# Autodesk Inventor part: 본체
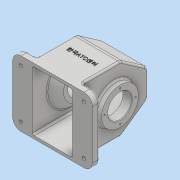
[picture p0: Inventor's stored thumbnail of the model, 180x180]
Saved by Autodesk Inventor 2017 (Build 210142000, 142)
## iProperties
Part Number: 본체
Material: 일반
Document SubType Name: Modeling
Designer: MRC
Density: 1 g/cm^3
Appearance: 기본값
Author: MRC
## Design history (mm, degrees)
sketch "스케치4"
  geometry: L1 (38.5, -55)-(-38.5, -55); L2 (-38.5, -55)-(-38.5, 55); L3 (-38.5, 55)-(38.5, 55); L4 (38.5, 55)-(38.5, -55); L5 (38.5, -55)-(-38.5, 55); L6 (-38.5, -55)-(38.5, 55); 1 further point
  constraints: 12 end point, 2 midpoint, 2 parallel, 1 horizontal, 1 perpendicular
  dimensions: "d12" = 110 distance of L3.end L1.start; "d13" = 77 distance of L1.start L1.end
extrude "돌출4" new body sketch "스케치4" distance "d14" = 122; taper "d15" = 0 deg
sketch "스케치5"
  geometry: L1 (0, 77)-(31.509, 122); L2 (0, 0)-(0, 122) reference; L3 (110, 0)-(0, 0) reference; L4 (0, 122)-(110, 122) reference; 1 further point
  constraints: 2 end point, 2 point on line
  dimensions: "d16" = 35 deg angle of L1 L2; "d17" = 77 distance from line of L3 L1.start
extrude "돌출5" cut sketch "스케치5" distance "d18" = 122; taper "d19" = 0 deg
feature "쉘1" dims "d20" = 5
sketch "스케치7"
  geometry: L1 (-38.5, 55)-(-38.5, -55) reference; L2 (38.5, 55)-(-38.5, 55) reference; L3 (-38.5, 55)-(-67, 55); L4 (-67, 55)-(-67, -55); L5 (-38.5, -55)-(38.5, -55) reference; L6 (-67, -55)-(-38.5, -55); 1 further point
  constraints: 6 end point, 2 perpendicular, 1 horizontal
  dimensions: "d25" = 67 distance from line of L4 point (0, 0)
extrude "돌출7" join sketch "스케치7" distance "d26" = 12; taper "d27" = 0 deg
node "작업 평면1"
sketch "스케치8"
  geometry: L1 (-26.509, -122)-(73.491, -122) reference; C1 r 37.5 at (23.491, -57); 1 further point
  constraints: 1 centre point, 1 vertical alignment
  dimensions: "d29" = 75 diameter of C1; "d30" = 65 distance from line of L1 C1.centre
extrude "돌출8" join sketch "스케치8" stored distance "d31" = 12; taper "d32" = 0 deg
sketch "스케치9"
  geometry: L1 (-55, -65)-(55, -65) reference; C1 r 37.5 at (0, 0) reference; 3 further points
  constraints: 1 midpoint, 1 vertical alignment
  dimensions: "d33" = 29 distance of C1.centre point (0, 29)
hole "구멍1" sketch "스케치9" at (0, 29) diameter "d34" = 2.459; stored, may be unused: countersink angle "d38" = 90 deg, drill point angle "d40" = 118 deg; dims "d35" = 6, "d36" = 4, "d37" = 2, "d39" = 8
node "작업 평면2"
sketch "스케치10"
  geometry: L1 (78.491, -122)-(-31.509, -122) reference; C1 r 31 at (23.491, -57); 2 further points
  constraints: 1 centre point, 1 midpoint, 1 vertical alignment
  dimensions: "d45" = 62 diameter of C1; "d46" = 65 distance from line of C1.centre L1
extrude "돌출9" join sketch "스케치10" distance "d47" = 10; taper "d48" = 0 deg
sketch "스케치11"
  geometry: C1 r 31 at (0, 0) reference; 2 further points
  constraints: 1 vertical alignment
  dimensions: "d49" = 26 distance of C1.centre point (0, 26)
hole "구멍2" sketch "스케치11" at (0, 26) diameter "d50" = 2.459; stored, may be unused: countersink angle "d54" = 90 deg, drill point angle "d56" = 118 deg; dims "d51" = 6, "d52" = 4, "d53" = 2, "d55" = 8
node "작업 평면3"
sketch "스케치13"
  geometry: C1 r 31 at (0, 0) reference; C2 r 27 at (0, 0); 1 further point
  constraints: 1 centre point, 1 coincident
  dimensions: "d63" = 54 diameter of C2
extrude "돌출10" join sketch "스케치13" stored distance "d64" = 10; taper "d65" = 45 deg
hole "구멍3" diameter "d68" = 40; stored, may be unused: countersink angle "d72" = 90 deg, drill point angle "d74" = 118 deg; dims "d66" = 10, "d67" = 10, "d69" = 6, "d70" = 4, "d71" = 2, "d73" = 8
fillet "모깎기1" dims "d75" = 14
sketch "스케치14"
  geometry: A1 r 14 centre (-53, 41) between (-53, 55) and (-67, 41) reference; A2 r 14 centre (53, 41) between (67, 41) and (53, 55) reference; A3 r 14 centre (53, -41) between (53, -55) and (67, -41) reference; A4 r 14 centre (-53, -41) between (-67, -41) and (-53, -55) reference; 5 further points
  constraints: 4 coincident
hole "구멍4" sketch "스케치14" at (-53, 41), (53, 41), (53, -41), (-53, -41) diameter "d76" = 5.5; stored, may be unused: countersink angle "d80" = 90 deg, drill point angle "d82" = 118 deg; dims "d77" = 6, "d78" = 15, "d79" = 2, "d81" = 8
node "작업 평면4"
sketch "스케치15"
  geometry: L1 (38.5, -55)-(-38.5, -55) reference; L2 (38.5, -23.491)-(38.5, -55) reference; C1 r 6 at (0, 0); 1 further point
  constraints: 1 centre point
  dimensions: "d87" = 12 diameter of C1; "d88" = 38.5 distance from line of C1.centre L2; "d89" = 55 distance from line of C1.centre L1
extrude "돌출11" join sketch "스케치15" stored distance "d90" = 10; taper "d91" = 0 deg
hole "구멍5" diameter "d94" = 5.188; stored, may be unused: countersink angle "d98" = 90 deg, drill point angle "d100" = 118 deg; dims "d92" = 10, "d93" = 10, "d95" = 12, "d96" = 1, "d97" = 2, "d99" = 16
sketch "스케치16"
  geometry: L1 (-14.5, -77)-(-28.5, -77) reference; L2 (0, -65)-(0, 0) reference; 2 further points
  constraints: 1 other
  dimensions: "d101" = 50 distance from line of L1 point (38.5, -27); "d102" = 38.5 distance from line of point (38.5, -27) L2
feature "엠보싱1" sketch "스케치16" dims "d12" = 110, "d13" = 77, "d103" = 0.5, "d104" = 0
fillet "모깎기2" dims "d105" = 10
chamfer "모따기1" distance "d107" = 1; stored, may be unused: second distance "d108" = 2, angle "d109" = 45 deg
fillet "모깎기4" dims "d110" = 5
fillet "모깎기5" dims "d111" = 3
node "솔리드2"
mirror "미러2"
mirror "미러3"
pattern_circular "원형 패턴1" dims angle "d42" = 360 deg
pattern_circular "원형 패턴2" dims angle "d58" = 360 deg
other parameters: "d28" = 5, "d62" = -24, "d83" = 126
